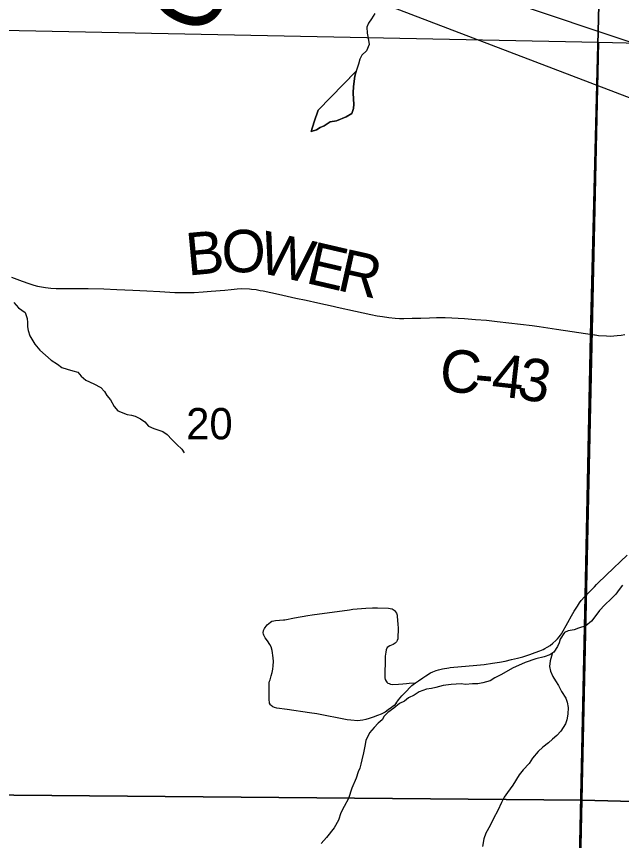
# Model space of a CAD drawing. Extents: x -7.1 to 34, y 0 to 22.
# Drawn here: x 5.914 to 6.724, y 15.673 to 16.774 of the extents above; entities that cross this region are included whole.
import ezdxf

# ---------------------------------------------------------------- set-up
doc = ezdxf.new("R2010")
doc.units = 0
for name, color, linetype in [('GM_X_County_Road', 7, 'Continuous'), ('GM_X_County_Road_Text', 7, 'Continuous'), ('GM_X_Major_River_Text', 7, 'Continuous'), ('GM_X_Minor_River', 7, 'Continuous'), ('GM_X_Section', 7, 'Continuous'), ('GM_X_Section_Text', 7, 'Continuous'), ('GM_X_Township_Road', 7, 'Continuous'), ('SH_Text', 7, 'Continuous')]:
    doc.layers.add(name, color=color, linetype=linetype)

msp = doc.modelspace()

# ---------------------------------------------------------------- linework, layer by layer
at = {"layer": 'GM_X_County_Road'}
for points in [[(5.9074, 16.4257), (5.9221, 16.4204), (5.9308, 16.4174), (5.9376, 16.4154), (5.9426, 16.414), (5.9477, 16.4129), (5.9533, 16.4121), (5.9604, 16.4113), (5.9672, 16.4109), (5.976, 16.4107), (6.0101, 16.4106), (6.0309, 16.4101), (6.0484, 16.4096), (6.0701, 16.4087), (6.0887, 16.4078), (6.1059, 16.4068), (6.1262, 16.4056), (6.1319, 16.4054), (6.1521, 16.4056), (6.1641, 16.4062), (6.1748, 16.407), (6.1929, 16.4087), (6.2015, 16.4096), (6.2094, 16.4102), (6.2157, 16.4106), (6.2258, 16.4103), (6.2288, 16.41), (6.2347, 16.4093), (6.24, 16.4083), (6.2442, 16.4076), (6.2544, 16.4053), (6.2646, 16.4031), (6.2765, 16.4004), (6.2878, 16.398), (6.3016, 16.395), (6.3175, 16.3915), (6.3378, 16.3871), (6.3432, 16.3859), (6.3676, 16.3806), (6.3884, 16.376), (6.3968, 16.3743), (6.404, 16.3731), (6.4122, 16.3719), (6.421, 16.371), (6.4268, 16.3707), (6.4325, 16.3705), (6.4435, 16.3709), (6.4549, 16.3712), (6.4665, 16.3716), (6.4761, 16.3718), (6.4876, 16.3719), (6.4967, 16.3716), (6.5137, 16.3706), (6.5282, 16.3695), (6.543, 16.3682), (6.5573, 16.3666), (6.6041, 16.3612), (6.6136, 16.3599), (6.6364, 16.3566), (6.6872, 16.3487), (6.6881, 16.3486)], [(6.6881, 16.3486), (6.6926, 16.3481), (6.7035, 16.3473), (6.709, 16.3472), (6.7133, 16.3474), (6.7178, 16.3477), (6.7232, 16.3483), (6.728, 16.3491)]]:
    msp.add_lwpolyline(points, dxfattribs=at)
at = {"layer": 'GM_X_Minor_River'}
for points in [[(6.3938, 16.7784), (6.389, 16.7714), (6.3853, 16.7657), (6.3831, 16.7603), (6.3832, 16.7523), (6.3852, 16.7428), (6.3861, 16.7368), (6.3824, 16.7287), (6.3764, 16.7229), (6.3735, 16.7175), (6.3717, 16.7106), (6.3691, 16.7026), (6.367, 16.6946), (6.3649, 16.6808), (6.3647, 16.6725), (6.3652, 16.6641), (6.3656, 16.6573), (6.365, 16.6512), (6.3628, 16.6446), (6.3553, 16.6403), (6.3421, 16.6348), (6.3338, 16.6336), (6.3259, 16.6281), (6.3206, 16.6261), (6.3154, 16.623), (6.3086, 16.6206), (6.3126, 16.6336), (6.3177, 16.6493), (6.3684, 16.7011)], [(6.3086, 16.6206), (6.3154, 16.623), (6.3206, 16.6261), (6.3259, 16.6281), (6.3338, 16.6336), (6.3421, 16.6348), (6.3553, 16.6403), (6.3628, 16.6446), (6.365, 16.6512), (6.3656, 16.6573), (6.3652, 16.6641), (6.3647, 16.6725), (6.3649, 16.6808), (6.367, 16.6946), (6.3688, 16.7015)], [(6.3688, 16.7015), (6.3177, 16.6493), (6.3126, 16.6336), (6.3086, 16.6206)], [(5.9106, 16.3919), (5.9171, 16.3848), (5.9259, 16.3788), (5.9287, 16.3705), (5.9292, 16.3655), (5.9292, 16.3594), (5.9301, 16.3545), (5.9321, 16.3473), (5.939, 16.3364), (5.9456, 16.3281), (5.9605, 16.315), (5.969, 16.3098), (5.9751, 16.3053), (5.9819, 16.3027), (5.9895, 16.3006), (5.9964, 16.2988), (6.001, 16.2935), (6.0071, 16.2883), (6.0178, 16.2835), (6.027, 16.2783), (6.032, 16.273), (6.0351, 16.2678), (6.0401, 16.2617), (6.0451, 16.2531), (6.0497, 16.2474), (6.0623, 16.2423), (6.068, 16.2412), (6.0729, 16.2402), (6.0802, 16.2365), (6.0859, 16.2323), (6.0909, 16.2267), (6.0978, 16.2234), (6.11, 16.2194), (6.1157, 16.2157), (6.1219, 16.2089), (6.1288, 16.2022), (6.1353, 16.1958), (6.1384, 16.1909)], [(6.7248, 16.014), (6.7203, 16.0082), (6.7159, 16.002), (6.7099, 15.9959), (6.7013, 15.9877), (6.6942, 15.9804), (6.6894, 15.9735), (6.6834, 15.9658), (6.6756, 15.9599), (6.6658, 15.9564), (6.6601, 15.9544), (6.6522, 15.9531), (6.6473, 15.9508), (6.6414, 15.9419), (6.6403, 15.9369), (6.6381, 15.932), (6.6329, 15.9247), (6.6277, 15.9211), (6.6202, 15.9184), (6.6088, 15.9155), (6.5945, 15.9107), (6.5776, 15.9033), (6.5629, 15.8947), (6.5543, 15.8903), (6.5479, 15.8864), (6.5381, 15.8836), (6.5313, 15.8824), (6.5241, 15.8823), (6.5147, 15.8814), (6.509, 15.882), (6.4958, 15.8811), (6.4852, 15.8798), (6.4754, 15.8773), (6.4693, 15.8761), (6.4629, 15.8749), (6.4527, 15.8713), (6.446, 15.867), (6.4385, 15.8635), (6.4332, 15.8592), (6.4265, 15.856), (6.419, 15.8495), (6.4111, 15.844), (6.4063, 15.839), (6.4033, 15.834), (6.3981, 15.8294), (6.3928, 15.8239), (6.3865, 15.8166), (6.3814, 15.8066), (6.38, 15.799), (6.3786, 15.7898), (6.3764, 15.7807), (6.375, 15.7749), (6.3736, 15.7696), (6.3714, 15.7646), (6.3685, 15.7562), (6.363, 15.7428), (6.3583, 15.729), (6.3524, 15.7183), (6.3483, 15.7098), (6.3451, 15.6999), (6.3391, 15.6895), (6.3291, 15.6768), (6.3217, 15.6687)], [(6.6312, 15.9235), (6.63, 15.9193), (6.6282, 15.9128), (6.6272, 15.9052), (6.6284, 15.8991), (6.6315, 15.8919), (6.6354, 15.8862), (6.6393, 15.8798), (6.6432, 15.8719), (6.649, 15.8632), (6.6509, 15.8576), (6.6522, 15.8507), (6.6519, 15.8416), (6.6502, 15.8339), (6.6487, 15.8286), (6.6424, 15.819), (6.6372, 15.8132), (6.6312, 15.8081), (6.626, 15.8035), (6.6181, 15.7973), (6.6122, 15.7915), (6.6047, 15.783), (6.5999, 15.7757), (6.5921, 15.7672), (6.5865, 15.7603), (6.578, 15.7468), (6.5709, 15.7368), (6.5668, 15.7307), (6.5632, 15.7234), (6.558, 15.713), (6.5525, 15.7023), (6.5477, 15.6927), (6.5422, 15.6823), (6.5396, 15.6751), (6.5375, 15.6647)]]:
    msp.add_lwpolyline(points, dxfattribs=at)
at = {"layer": 'GM_X_Section'}
for points in [[(5.6742, 16.7607), (6.6929, 16.7402), (6.6705, 15.7268), (5.6569, 15.7356)], [(7.7117, 16.7156), (7.6901, 15.7003), (6.6705, 15.7268), (6.6929, 16.7402)], [(6.6705, 15.7268), (6.6482, 14.7054), (5.6272, 14.7254), (5.6569, 15.7356)], [(7.6901, 15.7003), (7.6641, 14.6933), (6.6482, 14.7054), (6.6705, 15.7268)]]:
    msp.add_lwpolyline(points, close=True, dxfattribs=at)
at = {"layer": 'GM_X_Township_Road'}
for points in [[(2.1, 17.7253), (2.1, 14.1), (6.633, 14.1), (6.6565, 15.1357), (6.6586, 15.2372), (6.6748, 15.9993), (6.6822, 16.3488), (6.7058, 17.2839), (6.7118, 17.7486)], [(6.6902, 16.0148), (6.6916, 16.0162), (6.703, 16.0276), (6.7129, 16.0369), (6.722, 16.0456), (6.7309, 16.054)], [(6.6775, 16.002), (6.6834, 16.008), (6.6874, 16.012), (6.6902, 16.0148)], [(6.4223, 15.8564), (6.4253, 15.8606), (6.4276, 15.8636), (6.4299, 15.8662), (6.4324, 15.8689), (6.436, 15.8726), (6.4406, 15.8773), (6.4433, 15.8798), (6.4482, 15.8837), (6.4519, 15.8861), (6.458, 15.8904), (6.4619, 15.893), (6.4681, 15.8967), (6.4713, 15.8984), (6.4755, 15.9001), (6.4786, 15.901), (6.4841, 15.9023), (6.4924, 15.9036), (6.4945, 15.9039), (6.5301, 15.9072), (6.5397, 15.9081), (6.5509, 15.9096), (6.5602, 15.9111), (6.5679, 15.9126), (6.5766, 15.9145), (6.5846, 15.9165), (6.5917, 15.9185), (6.6007, 15.9214), (6.6079, 15.9239), (6.6141, 15.9263), (6.6186, 15.9282), (6.621, 15.9294), (6.6239, 15.931), (6.628, 15.9336), (6.6316, 15.9364), (6.6355, 15.9399), (6.6381, 15.9425), (6.6401, 15.9449), (6.6418, 15.9472), (6.6431, 15.9492), (6.6517, 15.9642), (6.6566, 15.9729), (6.6601, 15.9792), (6.6647, 15.9862), (6.6675, 15.9904), (6.6698, 15.9937), (6.6739, 15.9984), (6.6775, 16.002)], [(6.4223, 15.8564), (6.4193, 15.8533), (6.4157, 15.8504), (6.4115, 15.8472), (6.4072, 15.8442), (6.4019, 15.8417), (6.3971, 15.8398), (6.3915, 15.8377), (6.3859, 15.836), (6.3817, 15.8347), (6.3777, 15.8337), (6.3741, 15.8331), (6.3707, 15.8328), (6.3613, 15.8334), (6.3564, 15.8342), (6.3161, 15.8419), (6.3062, 15.8435), (6.2763, 15.8479), (6.2624, 15.8497), (6.2592, 15.8505), (6.257, 15.8515), (6.2551, 15.853), (6.2539, 15.8543), (6.2529, 15.8562), (6.2527, 15.8579), (6.2524, 15.8597), (6.2522, 15.8637), (6.2521, 15.8697), (6.2522, 15.8814), (6.2524, 15.8836), (6.2529, 15.8859), (6.2535, 15.8877), (6.2549, 15.8927), (6.2563, 15.8973), (6.2572, 15.902), (6.2578, 15.9063), (6.2579, 15.9121), (6.2575, 15.917), (6.2561, 15.9269), (6.2548, 15.9315), (6.2533, 15.9346), (6.2501, 15.9395), (6.2471, 15.9436), (6.2465, 15.9445), (6.2451, 15.9473), (6.2447, 15.9486), (6.2444, 15.9502), (6.2447, 15.9533), (6.2459, 15.9563), (6.2467, 15.9575), (6.2481, 15.9593), (6.2496, 15.9609), (6.2516, 15.9627), (6.2542, 15.9647), (6.256, 15.9659), (6.2583, 15.9664), (6.2606, 15.9669), (6.2662, 15.9673), (6.2715, 15.9677), (6.273, 15.9679), (6.2862, 15.9704), (6.304, 15.9736), (6.3096, 15.9743), (6.3599, 15.9812), (6.3643, 15.9818), (6.3817, 15.9832), (6.3905, 15.9836), (6.3971, 15.9838), (6.4118, 15.9835), (6.4143, 15.9831), (6.4166, 15.9824), (6.4182, 15.9816), (6.4193, 15.9808), (6.4202, 15.98), (6.4214, 15.9785), (6.4224, 15.9765), (6.4233, 15.9738), (6.4236, 15.9725), (6.4245, 15.9614), (6.4247, 15.9572), (6.4244, 15.9425), (6.4235, 15.9403), (6.4225, 15.9385), (6.4217, 15.9374), (6.4208, 15.9366), (6.4179, 15.9349), (6.4137, 15.9328), (6.4102, 15.9306), (6.4087, 15.9276), (6.4081, 15.9247), (6.4075, 15.9193), (6.4072, 15.9091), (6.4069, 15.8995), (6.4068, 15.8939), (6.4068, 15.8919), (6.4069, 15.8902), (6.4075, 15.8881), (6.4086, 15.8859), (6.4096, 15.8845), (6.4112, 15.8832), (6.4127, 15.8825), (6.4146, 15.8817), (6.4168, 15.8814), (6.4253, 15.8817), (6.4311, 15.8823), (6.4359, 15.8828), (6.4394, 15.8831), (6.4482, 15.8837)]]:
    msp.add_lwpolyline(points, dxfattribs=at)
msp.add_lwpolyline([(6.633, 14.1), (8.9, 14.1), (8.9, 17.7079), (8.6668, 17.7136), (8.4472, 17.7189), (7.7202, 17.7285), (6.7118, 17.7486), (6.7058, 17.2839), (6.6822, 16.3488), (6.6748, 15.9993), (6.6586, 15.2372), (6.6565, 15.1357)], close=True, dxfattribs=at)
at = {"layer": 'SH_Text'}
msp.add_lwpolyline([(5.1735, 17.2614), (9.3262, 15.8766), (9.3261, 15.6767)], close=True, dxfattribs=at)

# ---------------------------------------------------------------- texts
at = {"layer": 'GM_X_County_Road_Text'}
for s, rotation, p in [('B', 5.445, (6.1436, 16.4279)), ('O', 0.1785, (6.1886, 16.4323)), ('W', 347.5603, (6.2354, 16.4328)), ('E', 346.8836, (6.2995, 16.4186)), ('R', 347.3633, (6.3414, 16.4089)), ('C', 354.9232, (6.4787, 16.274)), ('4', 353.5334, (6.5481, 16.2677)), ('3', 350.4855, (6.5821, 16.2639)), ('-', 354.5978, (6.5251, 16.2699))]:
    msp.add_text(s, height=0.0568, rotation=rotation, dxfattribs=at).set_placement(p)
at = {"layer": 'GM_X_Major_River_Text'}
msp.add_text('Conotton', height=0.09472, rotation=63.5646, dxfattribs=at).set_placement((6.1668, 16.7422))
at = {"layer": 'GM_X_Section_Text'}
msp.add_text('20', height=0.04186, rotation=0, dxfattribs=at).set_placement((6.1412, 16.2091))

doc.saveas('drawing.dxf')
